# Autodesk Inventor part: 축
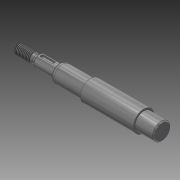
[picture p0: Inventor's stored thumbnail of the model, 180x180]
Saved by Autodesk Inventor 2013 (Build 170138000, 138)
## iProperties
Created: 2015-11
Part Number: 축
Material: 강철, 연강
Document SubType Name: Modeling
Designer: mduedu
Density: 1 g/cm^3
Author: mduedu
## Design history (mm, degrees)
sketch "스케치1"
  geometry: L1 (-86, 0)-(86, 0); L2 (-86, 0)-(-86, 4); L3 (-86, 4)-(-71.732, 4); L4 (-71.732, 4)-(-70, 3); L5 (-70, 3)-(-68, 3); L6 (-68, 3)-(-68, 5); L7 (-68, 5)-(-50, 5); L8 (-50, 5)-(-50, 6.55); L9 (-48.355, 7.5)-(-23, 7.5); L10 (-23, 7.5)-(-23, 9); L11 (0, 0)-(0, 9); L12 (86, 4)-(71.732, 4); L13 (71.732, 4)-(70, 3); L14 (70, 3)-(68, 3); L15 (68, 3)-(68, 5); L16 (68, 5)-(50, 5); L17 (23, 7.5)-(23, 9); L18 (86, 0)-(86, 4); L19 (-23, 9)-(23, 9); L20 (-50, 6.55)-(-48.355, 7.5); L21 (48.355, 7.5)-(23, 7.5); L22 (50, 6.55)-(48.355, 7.5); L23 (50, 5)-(50, 6.55); 1 further point
  constraints: 46 end point, 10 symmetric about line, 6 perpendicular, 5 parallel, 2 midpoint, 1 coincident, 1 horizontal
  dimensions: "d0" = 172 distance of L1.start L1.end (derived); "d1" = 8 diameter of L3 L1; "d2" = 30 deg angle of L4 L5; "d3" = 6 diameter of L5 L1; "d4" = 10 diameter of L7 L1; "d5" = 15 diameter of L9 L1; "d6" = 18 diameter of L19 L1; "d8" = 18 distance of L6.end L7.end; "d9" = 46 distance of L10.end L17.end; "d10" = 2 distance of L4.end L5.end; "d11" = 16 distance from line of L4.end L2; "d16" = 13.1 diameter of L8.end L1; "d17" = 30 deg angle of L20 L9; "d18" = 27 distance between parallel lines of L10 L8
revolve "회전1" sketch "스케치1" stored, may be unused: angle "d12" = 90 deg
chamfer "모따기1" distance "d13" = 1; stored, may be unused: second distance "d14" = 2, angle "d15" = 45 deg
fillet "모깎기1" dims "d19" = 4, "d20" = 0.5
node "작업 평면1"
sketch "스케치2" dims "d23" = 12
  geometry: L1 (-5.5, 1.5)-(3.5, 1.5); L2 (3.5, 1.5)-(3.5, -1.5); L3 (3.5, -1.5)-(-5.5, -1.5); L4 (-5.5, -1.5)-(-5.5, 1.5); L5 (-9, -4)-(-9, 4) reference; 3 further points
  constraints: 8 end point, 2 midpoint, 2 parallel, 2 vertical alignment, 1 horizontal, 1 perpendicular, 4 other
  dimensions: "d21" = 3 distance between parallel lines of L3 L1; "d24" = 2 dimension on L5
extrude "돌출1" cut sketch "스케치2" distance "d25" = 1.8; taper "d26" = 0 deg
feature "스레드1" dims "d27" = 10, "d28" = 0
feature "스레드2" dims "d29" = 10, "d30" = 0
chamfer "모따기2" distance "d31" = 1; stored, may be unused: second distance "d32" = 2, angle "d33" = 45 deg
node "작업 평면2"
sketch "스케치3"
  geometry: C1 r 7.5 at (0, 0) reference; 1 further point
extrude "돌출2" cut sketch "스케치3" stored distance "d36" = 10; taper "d37" = 0 deg
chamfer "모따기3" distance "d38" = 1; stored, may be unused: second distance "d39" = 2, angle "d40" = 45 deg
node "솔리드1"
mirror "대칭1"
node "절단 모서리 투영1"
other parameters: "d35" = 16
